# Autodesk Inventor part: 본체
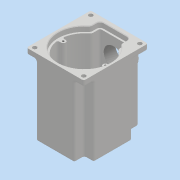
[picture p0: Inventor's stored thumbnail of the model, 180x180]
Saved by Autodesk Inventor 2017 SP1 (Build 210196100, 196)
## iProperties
Part Number: 본체
Material: 일반
Document SubType Name: Modeling
Designer: MRC
Density: 1 g/cm^3
Appearance: 기본값
Author: MRC
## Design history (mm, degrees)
sketch "스케치1"
  geometry: L1 (-49, -50)-(49, -50); L2 (49, -50)-(49, 60); L3 (49, 60)-(-49, 60); L4 (-49, 60)-(-49, -50); L5 (-49, -50)-(49, 60); L6 (49, -50)-(-49, 60); 3 further points
  constraints: 12 end point, 3 midpoint, 2 parallel, 1 horizontal, 1 perpendicular, 1 vertical alignment
  dimensions: "d0" = 98 distance of L2.end L3.end; "d1" = 110 distance of L3.end L1.start; "d2" = 50 distance from line of point (0, 0) L1
extrude "돌출1" new body sketch "스케치1" distance "d3" = 130; taper "d4" = 0 deg
sketch "스케치2"
  geometry: L1 (-26, 53)-(26, 53); L2 (26, 53)-(26, 28); L3 (26, 28)-(-26, 28); L4 (-26, 28)-(-26, 53); L5 (-26, 53)-(26, 28); L6 (26, 53)-(-26, 28); C1 r 45 at (0, 0); 3 further points
  constraints: 12 end point, 3 midpoint, 2 parallel, 1 centre point, 1 coincident, 1 horizontal, 1 perpendicular, 1 vertical alignment
  dimensions: "d5" = 52 distance of L1.start L1.end; "d6" = 90 diameter of C1; "d7" = 53 distance from line of L1 point (0, 0); "d8" = 25 distance of L3.end L1.start
extrude "돌출2" cut sketch "스케치2" distance "d9" = 9; taper "d10" = 0 deg
sketch "스케치3"
  geometry: L1 (26, 53)-(26, 36.729) reference; L2 (-26, 53)-(26, 53) reference; L3 (-26, 36.729)-(-26, 53) reference; L4 (26, 36.729)-(26, 53) reference; L5 (26, 53)-(-26, 53) reference; L6 (-26, 53)-(-26, 36.729) reference; L7 (49, 60)-(49, -50) reference; L8 (49, -50)-(-49, -50) reference; L9 (-49, -50)-(-49, 60) reference; L10 (-49, 60)-(49, 60) reference; L11 (-23, 50)-(23, 50); L12 (-23, 35.143)-(-23, 50); L13 (23, 50)-(23, 35.143); L14 (-36, 4)-(-41.809, 4); L15 (-36, -4)-(-41.809, -4); A1 r 45 centre (0, 0) between (-26, 36.729) and (26, 36.729) reference; A2 r 45 centre (0, 0) between (-26, 36.729) and (26, 36.729) reference; A3 r 42 centre (0, 0) between (-23, 35.143) and (23, 35.143); A4 r 4 centre (-36, 0) between (-36, -4) and (-36, 4)
  constraints: 10 end point, 6 point on circle, 4 parallel, 2 centre point, 2 horizontal, 2 tangent, 1 horizontal alignment
  dimensions: "d11" = 3 distance between parallel lines of L2 L11; "d12" = 3 distance between parallel lines of L3 L12; "d14" = 3 radial gap between concentric circles of A1 A3; "d15" = 3 distance between parallel lines of L1 L13; "d16" = 8 diameter of A4; "d18" = 36 distance of A4.centre A1.centre
  node "절단 모서리 투영1"
extrude "돌출3" cut sketch "스케치3" distance "d20" = 112; taper "d21" = 0 deg
extrude "돌출4" join sketch "스케치3" stored distance "d22" = 112; taper "d23" = 0 deg
sketch "스케치4"
  geometry: A1 r 42 centre (0, 0) between (41.809, 4) and (23, 35.143) reference; A2 r 42 centre (0, 0) between (-23, 35.143) and (-41.809, 4) reference; A3 r 21 centre (0, 11) between (8.978, -7.984) and (-8.978, -7.984); A4 r 15 centre (0, -20) between (-8.978, -7.984) and (8.978, -7.984)
  constraints: 4 point on circle, 2 centre point, 2 vertical alignment
  dimensions: "d27" = 42 diameter of A3; "d28" = 30 diameter of A4; "d29" = 11 distance of A3.centre A2.centre; "d30" = 20 distance of A1.centre A4.centre
extrude "돌출5" join sketch "스케치4" distance "d31" = 7; taper "d32" = 0 deg
hole "구멍1" diameter "d35" = 19; stored, may be unused: countersink angle "d39" = 90 deg, drill point angle "d41" = 0 deg; dims "d33" = 10, "d34" = 10, "d36" = 6, "d37" = 22, "d38" = 7, "d40" = 10
hole "구멍2" diameter "d44" = 28; stored, may be unused: countersink angle "d48" = 90 deg, drill point angle "d50" = 0 deg; dims "d42" = 10, "d43" = 10, "d45" = 6, "d46" = 35, "d47" = 10, "d49" = 10
sketch "스케치5"
  geometry: C1 r 14 at (0, 11) reference; C2 r 27 at (0, 11); 1 further point
  constraints: 1 centre point, 1 coincident
  dimensions: "d51" = 54 diameter of C2
extrude "돌출6" join sketch "스케치5" distance "d52" = 7; taper "d53" = 0 deg
sketch "스케치6"
  geometry: C1 r 14 at (0, 0) reference; C2 r 27 at (0, 0) reference; C3 r 16 at (0, 0); 1 further point
  constraints: 1 centre point, 1 coincident
  dimensions: "d54" = 32 diameter of C3
extrude "돌출7" cut sketch "스케치6" distance "d55" = 8.3; taper "d56" = 0 deg
sketch "스케치7"
  geometry: L1 (98, 0)-(0, 0) reference; C1 r 23 at (49, 40); 2 further points
  constraints: 1 centre point, 1 midpoint, 1 vertical alignment
  dimensions: "d57" = 46 diameter of C1; "d58" = 40 distance of point (49, 0) C1.centre
extrude "돌출8" join sketch "스케치7" distance "d59" = 10; taper "d60" = 0 deg
sketch "스케치8"
  geometry: L1 (98, 0)-(0, 0) reference; C1 r 23 at (49, 40) reference; C2 r 15 at (49, 89); 2 further points
  constraints: 1 centre point, 1 midpoint, 1 vertical alignment
  dimensions: "d61" = 30 diameter of C2; "d62" = 49 distance of C2.centre C1.centre
extrude "돌출9" join sketch "스케치8" distance "d63" = 5; taper "d64" = 0 deg
hole "구멍3" diameter "d67" = 20; stored, may be unused: countersink angle "d71" = 90 deg, drill point angle "d73" = 0 deg; dims "d65" = 10, "d66" = 10, "d68" = 6, "d69" = 35, "d70" = 10, "d72" = 10
sketch "스케치9"
  geometry: C1 r 10 at (23, -80) reference; C2 r 15 at (23, -80); 1 further point
  constraints: 1 centre point, 1 coincident
  dimensions: "d74" = 30 diameter of C2
extrude "돌출10" cut sketch "스케치9" distance "d75" = 5; taper "d76" = 0 deg
hole "구멍4" diameter "d79" = 33.376; stored, may be unused: countersink angle "d83" = 90 deg, drill point angle "d85" = 0 deg; dims "d77" = 10, "d78" = 10, "d80" = 40, "d81" = 35, "d82" = 10, "d84" = 77.3
hole "구멍5" diameter "d88" = 3.242; stored, may be unused: countersink angle "d92" = 90 deg, drill point angle "d94" = 118 deg; dims "d86" = 10, "d87" = 10, "d89" = 7, "d90" = 35, "d91" = 10, "d93" = 9
sketch "스케치10"
  geometry: L1 (49, 60)-(33, 60); L2 (33, 60)-(33, 33); L3 (33, 33)-(49, 33); L4 (49, 33)-(49, 60); L5 (-49, 60)-(-33, 60); L6 (-33, 60)-(-33, 33); L7 (-33, 33)-(-49, 33); L8 (-49, 33)-(-49, 60); 1 further point
  constraints: 16 end point, 4 parallel, 2 equal length, 2 horizontal, 2 perpendicular
  dimensions: "d98" = 27 distance of L1.end L2.end; "d99" = 16 distance of L6.end L7.end
extrude "돌출11" cut sketch "스케치10" distance "d100" = 120; taper "d101" = 0 deg
sketch "스케치11"
  geometry: L1 (49, -50)-(33, -50); L2 (33, -50)-(33, -33); L3 (33, -33)-(49, -33); L4 (49, -33)-(49, -50); L5 (-49, -50)-(-33, -50); L6 (-33, -50)-(-33, -33); L7 (-33, -33)-(-49, -33); L8 (-49, -33)-(-49, -50); 1 further point
  constraints: 16 end point, 4 parallel, 2 equal length, 2 horizontal, 2 perpendicular
  dimensions: "d102" = 16 distance of L2.end L3.end; "d103" = 17 distance of L1.end L2.end
extrude "돌출12" cut sketch "스케치11" distance "d104" = 120; taper "d105" = 0 deg
sketch "스케치12"
  geometry: L1 (-49, 60)-(-33, 60) reference; C1 r 3.5 at (-42, 53); C2 r 3.5 at (42, 53); C3 r 3.5 at (42, -43); C4 r 3.5 at (-42, -43); 1 further point
  constraints: 4 centre point, 3 equal radius, 2 horizontal alignment, 2 vertical alignment
  dimensions: "d106" = 7 diameter of C1; "d107" = 84 distance of C2.centre C1.centre; "d108" = 96 distance of C1.centre C4.centre; "d109" = 42 horizontal distance of point (0, 0) C1.centre; "d111" = 7 distance from line of L1 C1.centre
extrude "돌출13" cut sketch "스케치12" stored distance "d112" = 120; taper "d113" = 0 deg
sketch "스케치13"
  geometry: L1 (-27, -27)-(27, -27); L2 (27, -27)-(27, 27); L3 (27, 27)-(-27, 27); L4 (-27, 27)-(-27, -27); L5 (-27, -27)-(27, 27); L6 (27, -27)-(-27, 27); C1 r 16 at (0, 0) reference; C2 r 27 at (0, 0) reference; C3 r 16 at (0, 0) reference; C4 r 27 at (0, 0) reference; C5 r 16 at (0, 0) reference; C6 r 27 at (0, 0) reference; 1 further point
  constraints: 12 end point, 2 midpoint, 2 parallel, 1 horizontal, 1 perpendicular
  dimensions: "d114" = 54 distance of L2.end L3.end; "d115" = 54 distance of L3.end L1.start
extrude "돌출14" join sketch "스케치13" stored distance "d116" = 120; taper "d117" = 0 deg
chamfer "모따기1" distance "d118" = 0.8; stored, may be unused: second distance "d119" = 2, angle "d120" = 30 deg
fillet "모깎기1" dims "d121" = 0.3
fillet "모깎기2" dims "d125" = 0.3
fillet "모깎기3" dims "d126" = 3
fillet "모깎기8" dims "d138" = 6
fillet "모깎기4" dims "d127" = 3
fillet "모깎기5" dims "d128" = 3
fillet "모깎기6" dims "d129" = 3
fillet "모깎기7" dims "d130" = 6
chamfer "모따기2" distance "d122" = 1; stored, may be unused: second distance "d123" = 2, angle "d124" = 30 deg
node "작업 평면2"
sketch "스케치16"
  geometry: L1 (-130, 104)-(-130, 83) reference; L2 (-13, 80)-(-127, 80) reference; 2 further points
  constraints: 1 other
  dimensions: "d134" = 65 distance from line of L1 point (-65, 47); "d135" = 33 distance from line of L2 point (-65, 47)
feature "엠보싱1" sketch "스케치16" dims "d136" = 0.5, "d137" = 0
node "솔리드1"
pattern_circular "원형 패턴1" dims angle "d25" = 360 deg
pattern_circular "원형 패턴2" dims angle "d96" = 360 deg
node "절단 모서리 투영2"
node "절단 모서리 투영3"
other parameters: "d133" = 140.5
